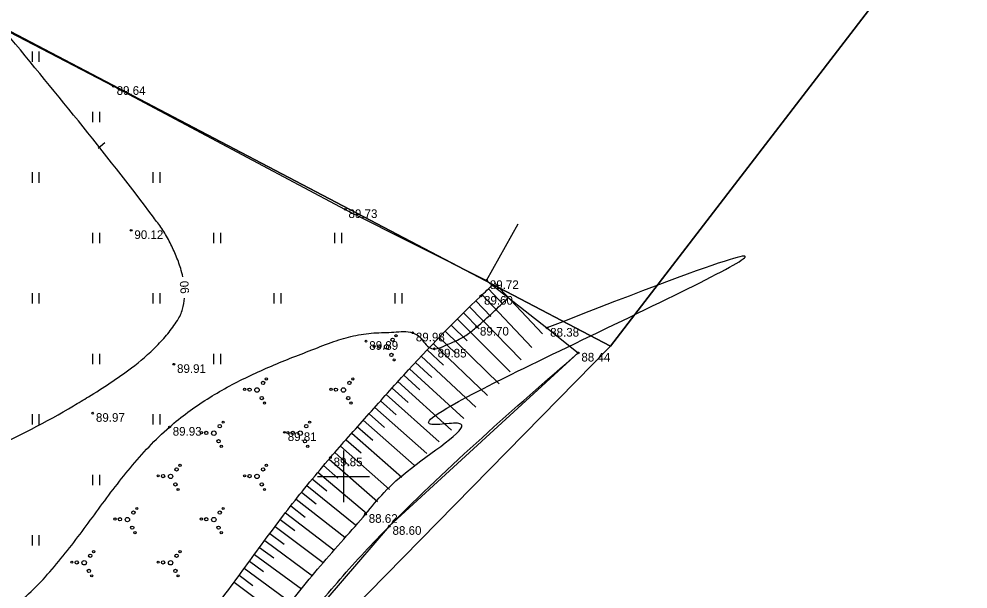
# Model space of a CAD drawing. Extents: x 635228 to 635525, y 248590 to 248800.
# Drawn here: x 635431.2 to 635486.1, y 248693.5 to 248726.5 of the extents above; entities that cross this region are included whole.
import ezdxf

# ---------------------------------------------------------------- set-up
doc = ezdxf.new("R2010")
doc.units = 0
for name, color, linetype in [('GEOD_ELEM_####_####_#', 7, 'Continuous'), ('HIDG_GRAV_####_####_#', 7, 'Continuous'), ('NORB_ZOGS_ZSTP_####_#', 7, 'Continuous'), ('RAMI_UZMR_####_####_#', 7, 'Continuous'), ('RELJ_AATZ_####_TKST_#', 7, 'Continuous'), ('RELJ_ELEM_####_####_#', 7, 'Continuous'), ('RELJ_HORZ_####_TKST_#', 7, 'Continuous'), ('RELJ_HORZ_RESN_####_#', 7, 'Continuous'), ('RELJ_NOGA_####_####_#', 7, 'Continuous'), ('ROBZ_IERR_####_####_#', 7, 'Continuous'), ('ROBZ_UZMR_####_####_#', 7, 'Continuous'), ('TERT_ELEM_####_####_#', 7, 'Continuous'), ('TERT_KONT_####_####_#', 7, 'Continuous')]:
    doc.layers.add(name, color=color, linetype=linetype)

msp = doc.modelspace()

# ---------------------------------------------------------------- linework, layer by layer
at = {"layer": 'GEOD_ELEM_####_####_#'}
for p, q in [((635450, 248701.5), (635450, 248700)), ((635448.5, 248700), (635450, 248700)), ((635450, 248700), (635450, 248698.5)), ((635450, 248700), (635451.5, 248700))]:
    msp.add_line(p, q, dxfattribs=at)
at = {"layer": 'HIDG_GRAV_####_####_#'}
for points in [[(635394.244, 248623.295), (635394.9074355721, 248630.6631552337), (635396.5650242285, 248636.944974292), (635397.8888882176, 248639.97580624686), (635399.2686043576, 248642.98780740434), (635400.0423829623, 248644.69884236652), (635400.835233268, 248646.3905777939), (635402.4795660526, 248649.72803076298), (635404.20443685, 248653.0239277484), (635406.0126797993, 248656.30203018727), (635407.0670223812, 248658.14081276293), (635408.1930324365, 248659.92698593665), (635409.4621962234, 248661.60192368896), (635410.172800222, 248662.37935865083), (635410.946, 248663.10700000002), (635413.0008032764, 248664.6744257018), (635415.1640977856, 248666.05372522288), (635417.3478434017, 248667.38916213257), (635419.464, 248668.825), (635422.2083511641, 248670.85354035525), (635424.965867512, 248672.86854694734), (635430.4558647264, 248676.93578902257), (635435.8049295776, 248681.1823865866), (635438.3862804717, 248683.4215875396), (635439.6466024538, 248684.57867623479), (635440.8840000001, 248685.76400000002), (635443.6087249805, 248688.6747140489), (635446.1599310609, 248691.73220612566), (635448.6719216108, 248694.81834513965), (635451.279, 248697.815), (635453.9336502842, 248700.48189136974), (635456.6811388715, 248703.07136968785), (635459.3523080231, 248705.7266631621), (635461.7780000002, 248708.59100000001), (635461.778, 248708.59100000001)], [(635396.7397638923, 248625.2320466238), (635397.9986579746, 248634.27312358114), (635398.9188026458, 248636.96227546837), (635399.5920874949, 248638.24717771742), (635399.9292604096, 248638.88899780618), (635400.2466831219, 248639.53584001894), (635401.591165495, 248642.41958219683), (635402.9524948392, 248645.2868638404), (635405.8217854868, 248650.96088254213), (635407.5583128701, 248653.91205967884), (635409.4799859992, 248656.7354955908), (635411.5283407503, 248659.48290512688), (635413.6449129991, 248662.20600313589), (635414.8182615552, 248663.6538935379), (635415.4704678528, 248664.3057478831), (635416.2076616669, 248664.85985159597), (635417.1601741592, 248665.41138033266), (635418.1313630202, 248665.91742947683), (635419.1067857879, 248666.41122678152), (635420.072, 248666.926), (635421.5645353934, 248667.7418115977), (635423.0692260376, 248668.5354410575), (635426.0762392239, 248670.12612318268), (635429.0153718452, 248671.8379856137), (635430.4352117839, 248672.78309045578), (635431.128452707, 248673.2855892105), (635431.8089561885, 248673.81096758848), (635433.1953696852, 248675.0040709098), (635434.526751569, 248676.2563297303), (635437.0226234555, 248678.92292892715), (635441.762, 248684.467), (635443.1273679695, 248686.0473501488), (635444.4678763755, 248687.6485508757), (635447.1219662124, 248690.87245996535), (635449.819572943, 248694.05663907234), (635451.2144774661, 248695.60817732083), (635452.6560000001, 248697.119), (635458.0231966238, 248702.2419696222), (635463.584, 248707.15000000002)]]:
    msp.add_spline(points, degree=3, dxfattribs=at)
at = {"layer": 'NORB_ZOGS_ZSTP_####_#'}
msp.add_lwpolyline([(635360.648, 248762.312), (635368.914, 248758.068), (635380.222, 248751.913), (635388.377, 248747.78900000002), (635390.826, 248746.16), (635396.2860000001, 248743.48500000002), (635409.766, 248736.46000000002), (635417.8699999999, 248732.30000000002), (635426.003, 248728.155), (635436.69, 248722.584), (635450.108, 248715.45700000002), (635458.287, 248711.34600000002), (635460.1128222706, 248714.62474159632)], dxfattribs=at)
at = {"layer": 'RAMI_UZMR_####_####_#'}
msp.add_lwpolyline([(635426.003, 248728.15499999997), (635436.69, 248722.584), (635450.108, 248715.45700000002), (635458.287, 248711.34600000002), (635461.7780000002, 248708.59100000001), (635463.584, 248707.15000000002), (635452.6560000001, 248697.119), (635441.762, 248684.467), (635435.9528772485, 248677.73413872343), (635432.018527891, 248673.97985762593), (635429.363741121, 248672.06248825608), (635427.0556775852, 248670.66460585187), (635420.072, 248666.926), (635415.05332695, 248664.00973325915), (635408.095218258, 248654.65947737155), (635398.6701763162, 248636.43948679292), (635398.046283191, 248634.41686083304), (635396.3166782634, 248622.87374513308), (635394.244, 248623.295), (635390.206, 248622.483), (635381.566, 248626.41900000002), (635379.918, 248627.738), (635364.657, 248634.36500000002)], dxfattribs=at)
at = {"layer": 'RELJ_ELEM_####_####_#'}
for centre in [(635436.69, 248722.584), (635450.108, 248715.45700000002), (635437.718, 248714.24300000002), (635458.287, 248711.34600000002), (635457.9500000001, 248710.44), (635457.714, 248708.652), (635454.0060000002, 248708.314), (635461.7780000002, 248708.59100000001), (635451.3080000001, 248707.82700000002), (635455.2640000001, 248707.383), (635463.584, 248707.15000000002), (635440.186, 248706.49000000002), (635435.4920000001, 248703.66100000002), (635439.936, 248702.85900000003), (635446.592, 248702.548), (635449.246, 248701.08800000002), (635451.279, 248697.815), (635452.6560000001, 248697.119)]:
    msp.add_circle(centre, 0.05, dxfattribs=at)
at = {"layer": 'RELJ_HORZ_RESN_####_#'}
msp.add_line((635435.8087515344, 248719.00655734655), (635436.1954663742, 248719.3234984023), dxfattribs=at)
for points in [[(635440.7152590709, 248711.54364329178), (635440.583994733, 248712.0305760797), (635440.2877567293, 248712.84067206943), (635440.1114035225, 248713.2345290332), (635439.9182199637, 248713.62218880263), (635439.7116635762, 248713.99309363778), (635439.4829756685, 248714.34956084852), (635439.0131516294, 248714.99704480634), (635430.1817186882, 248726.04739434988)], [(635396.8403365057, 248673.83023932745), (635398.5699520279, 248674.74721849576), (635400.1196081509, 248675.6687893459), (635401.3847631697, 248676.59316814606), (635401.8779834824, 248677.05585311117), (635402.2608753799, 248677.51857116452), (635402.5005008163, 248677.92779942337), (635402.9962003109, 248679.47940420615), (635403.1093939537, 248680.10527297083), (635403.2077718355, 248680.73304831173), (635403.3050539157, 248681.36081107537), (635403.4149601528, 248681.98664210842), (635403.9947087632, 248684.49620174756), (635404.4941894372, 248685.58182624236), (635404.822447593, 248686.0525951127), (635405.213, 248686.464), (635405.5227683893, 248686.49325254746), (635405.8948771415, 248686.27621660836), (635406.269797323, 248686.04907236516), (635406.588, 248686.048), (635407.1331532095, 248686.47133617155), (635407.6549224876, 248686.94769115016), (635408.6437981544, 248688.02779111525), (635410.511320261, 248690.47588617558), (635412.43838879, 248692.8856225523), (635414.0718482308, 248694.36296271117), (635414.672826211, 248694.7503376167), (635415.8418707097, 248695.38166460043), (635417.0157559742, 248695.99905223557), (635418.2014500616, 248696.5900310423), (635419.4059210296, 248697.14213154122), (635424.3998390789, 248699.29274669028), (635429.4588912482, 248701.50672660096), (635434.3873884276, 248704.0886148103), (635435.2434356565, 248704.60530447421), (635437.7315604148, 248706.27775516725), (635439.1970704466, 248707.5552960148), (635439.8338858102, 248708.26101524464), (635440.1227716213, 248708.63326282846), (635440.3898668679, 248709.01944554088), (635440.6922176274, 248709.6864690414), (635440.8034457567, 248710.32396866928)]]:
    msp.add_spline(points, degree=3, dxfattribs=at)
at = {"layer": 'RELJ_NOGA_####_####_#'}
for p, q in [((635458.7507877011, 248711.19532031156), (635461.5238321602, 248708.25534919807)), ((635458.0233306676, 248710.50916707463), (635460.8935670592, 248707.46615344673)), ((635458.3870591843, 248710.85224369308), (635459.2344702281, 248709.95382175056)), ((635457.300320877, 248709.81834287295), (635460.2761169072, 248706.74168752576)), ((635457.6605747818, 248710.16506404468), (635458.5384371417, 248709.24577131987)), ((635456.9427630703, 248709.4688411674), (635457.8515891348, 248708.54806386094)), ((635456.235110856, 248708.7622913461), (635457.1651303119, 248707.84622144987)), ((635456.587777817, 248709.11672723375), (635459.6533072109, 248706.04980383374)), ((635455.8847228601, 248708.4056016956), (635459.0067916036, 248705.36405206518)), ((635455.1904612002, 248707.6858868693), (635458.3372570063, 248704.6810007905)), ((635455.5365799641, 248708.046720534), (635456.4775242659, 248707.13883727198)), ((635454.8462935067, 248707.323191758), (635455.7922926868, 248706.42977421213)), ((635454.163237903, 248706.5928310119), (635455.1072428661, 248705.7167618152)), ((635454.5039056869, 248706.95881586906), (635457.6602966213, 248704.01217346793)), ((635453.8240771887, 248706.22544912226), (635456.9668449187, 248703.34344324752)), ((635453.1500941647, 248705.4867055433), (635456.2571430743, 248702.6705633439)), ((635453.4864578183, 248705.8566501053), (635454.4243257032, 248705.00166388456)), ((635452.8148920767, 248705.11570812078), (635453.7405111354, 248704.28141863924)), ((635452.1475016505, 248704.3710021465), (635453.058311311, 248703.55834299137)), ((635452.4807379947, 248704.74376640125), (635455.5423008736, 248701.99880622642)), ((635451.8150410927, 248703.99754573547), (635454.8240796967, 248701.32432924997)), ((635451.151874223, 248703.24907477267), (635454.1034339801, 248700.6434777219)), ((635451.4832108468, 248703.62352902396), (635452.3774163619, 248702.83198464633)), ((635450.8209720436, 248702.8742364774), (635451.6968263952, 248702.10104409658)), ((635450.1597600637, 248702.12403739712), (635451.0186125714, 248701.36717193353)), ((635450.4903386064, 248702.49916114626), (635453.3816116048, 248699.95122112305)), ((635449.8291815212, 248701.74891364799), (635452.6661222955, 248699.2488540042)), ((635449.4983825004, 248701.3739843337), (635450.3421288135, 248700.62937430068)), ((635448.8397843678, 248700.62150309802), (635449.6838531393, 248699.89911624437)), ((635449.1677142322, 248700.99893990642), (635451.9659276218, 248698.53924921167)), ((635448.516127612, 248700.24039430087), (635451.3338193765, 248697.87381566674)), ((635447.8803787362, 248699.46851923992), (635450.7080955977, 248697.18907648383)), ((635448.1964122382, 248699.85597317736), (635449.0439914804, 248699.1597187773)), ((635447.5676195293, 248699.07841672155), (635448.4144601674, 248698.40464081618)), ((635446.9512072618, 248698.2910043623), (635447.7955734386, 248697.638391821)), ((635447.2580275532, 248698.68579560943), (635450.0798587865, 248696.47854608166)), ((635446.6468800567, 248697.89428786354), (635449.4540488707, 248695.7508122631)), ((635446.3447459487, 248697.49589845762), (635447.1844750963, 248696.86229181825)), ((635445.7457224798, 248696.69517077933), (635446.5780655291, 248696.07709253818)), ((635446.0444019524, 248697.09615736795), (635448.8344916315, 248695.01405130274)), ((635445.4481811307, 248696.29333885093), (635448.2067325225, 248694.25382652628)), ((635445.1515740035, 248695.8908166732), (635445.9750107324, 248695.28585710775)), ((635444.559867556, 248695.08466325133), (635445.3719592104, 248694.48898971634)), ((635444.8555944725, 248695.48783268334), (635447.5820261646, 248693.487980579)), ((635444.2640867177, 248694.6815334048), (635446.9501521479, 248692.7079483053)), ((635443.6711792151, 248693.87626334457), (635446.3164226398, 248691.9252376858)), ((635443.9679659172, 248694.2786532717), (635444.7669883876, 248693.68932628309))]:
    msp.add_line(p, q, dxfattribs=at)
msp.add_spline([(635390.206, 248622.483), (635392.6761559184, 248639.41621940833), (635395.6724652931, 248647.2597307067), (635397.9131924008, 248650.95381667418), (635399.048256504, 248652.79837067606), (635400.128, 248654.662), (635400.9493075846, 248656.2558432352), (635403.3016292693, 248661.16811378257), (635405.1862207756, 248664.14373210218), (635407.706, 248666.499), (635412.1610828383, 248669.3503906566), (635416.627, 248672.168), (635424.6828055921, 248677.31078055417), (635432.728, 248682.47600000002), (635436.7060689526, 248685.70428438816), (635438.5008534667, 248687.5575466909), (635440.2150000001, 248689.48700000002), (635442.5291182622, 248692.3528262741), (635444.7219287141, 248695.30565037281), (635446.9190248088, 248698.24939928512), (635449.246, 248701.08800000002), (635451.3600052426, 248703.48451832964), (635453.4937434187, 248705.86484004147), (635457.9500000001, 248710.44), (635458.6576193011, 248711.10744185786)], degree=3, dxfattribs=at)
at = {"layer": 'ROBZ_IERR_####_####_#'}
for points in [[(635390.8703529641, 248797.67647954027), (635383.3870000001, 248769.68700000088), (635386.4840000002, 248768.44700000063), (635478.3770000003, 248731.65799999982), (635482.5609999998, 248729.82799999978), (635465.4589999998, 248707.53900000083), (635458.6069999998, 248711.13399999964), (635360.483, 248762.61500000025), (635360.8880000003, 248769.91799999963), (635363.3208497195, 248797.67647954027)], [(635522.337313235, 248635.85405923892), (635430.9589999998, 248667.77300000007), (635424.5429999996, 248670.01400000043), (635439.4570000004, 248681.03800000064), (635465.4589999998, 248707.53900000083), (635482.5609999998, 248729.82799999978), (635498.1289999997, 248747.85500000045)]]:
    msp.add_lwpolyline(points, dxfattribs=at)
at = {"layer": 'ROBZ_UZMR_####_####_#'}
msp.add_lwpolyline([(635325.5420000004, 248659.74000000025), (635329.6529999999, 248676.3660000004), (635327.79, 248676.82799999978), (635337.4600999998, 248688.65990000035), (635343.3430000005, 248703.1199999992), (635360.483, 248762.61500000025), (635458.6069999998, 248711.13399999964), (635465.4589999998, 248707.53900000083), (635439.4570000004, 248681.03800000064), (635424.5429999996, 248670.01400000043), (635420.9790000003, 248667.37900000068), (635407.0700000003, 248653.17999999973), (635400.0669999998, 248641.1490000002), (635395.1619999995, 248617.53900000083), (635389.0310000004, 248621.06200000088), (635375.858, 248629.11500000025)], close=True, dxfattribs=at)
at = {"layer": 'TERT_ELEM_####_####_#'}
for p, q in [((635432, 248724), (635432, 248724.6)), ((635432.4, 248724), (635432.4, 248724.6)), ((635435.5, 248720.5), (635435.5, 248721.1)), ((635435.9, 248720.5), (635435.9, 248721.1)), ((635432, 248717), (635432, 248717.6)), ((635432.4, 248717), (635432.4, 248717.6)), ((635439, 248717), (635439, 248717.6)), ((635439.4, 248717), (635439.4, 248717.6)), ((635435.5, 248713.5), (635435.5, 248714.1)), ((635435.9, 248713.5), (635435.9, 248714.1)), ((635442.5, 248713.5), (635442.5, 248714.1)), ((635442.9, 248713.5), (635442.9, 248714.1)), ((635449.5, 248713.5), (635449.5, 248714.1)), ((635449.9, 248713.5), (635449.9, 248714.1)), ((635432, 248710), (635432, 248710.6)), ((635432.4, 248710), (635432.4, 248710.6)), ((635439, 248710), (635439, 248710.6)), ((635439.4, 248710), (635439.4, 248710.6)), ((635446, 248710), (635446, 248710.6)), ((635446.4, 248710), (635446.4, 248710.6)), ((635453, 248710), (635453, 248710.6)), ((635453.4, 248710), (635453.4, 248710.6)), ((635435.5, 248706.5), (635435.5, 248707.1)), ((635435.9, 248706.5), (635435.9, 248707.1)), ((635442.5, 248706.5), (635442.5, 248707.1)), ((635442.9, 248706.5), (635442.9, 248707.1)), ((635432, 248703), (635432, 248703.6)), ((635432.4, 248703), (635432.4, 248703.6)), ((635439, 248703), (635439, 248703.6)), ((635439.4, 248703), (635439.4, 248703.6)), ((635435.5, 248699.5), (635435.5, 248700.1)), ((635435.9, 248699.5), (635435.9, 248700.1)), ((635432, 248696), (635432, 248696.6)), ((635432.4, 248696), (635432.4, 248696.6))]:
    msp.add_line(p, q, dxfattribs=at)
for centre, radius in [((635453.044, 248708.13935999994), 0.06400000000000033), ((635452.06608, 248707.52079999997), 0.09600000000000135), ((635452.5, 248707.5), 0.12800000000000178), ((635452.8475200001, 248707.90767999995), 0.09600000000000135), ((635451.7816, 248707.53423999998), 0.06400000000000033), ((635452.77648, 248707.03311999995), 0.09600000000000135), ((635452.93392, 248706.74383999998), 0.06400000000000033), ((635445.3475200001, 248705.40767999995), 0.09600000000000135), ((635445.544, 248705.63935999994), 0.06400000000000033), ((635450.3475200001, 248705.40767999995), 0.09600000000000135), ((635450.544, 248705.63935999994), 0.06400000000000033), ((635444.2816, 248705.03423999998), 0.06400000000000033), ((635444.56608, 248705.02079999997), 0.09600000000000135), ((635445, 248705), 0.12800000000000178), ((635449.2816, 248705.03423999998), 0.06400000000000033), ((635449.56608, 248705.02079999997), 0.09600000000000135), ((635450, 248705), 0.12800000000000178), ((635445.27648, 248704.53311999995), 0.09600000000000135), ((635445.43392, 248704.24383999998), 0.06400000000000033), ((635450.27648, 248704.53311999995), 0.09600000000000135), ((635450.43392, 248704.24383999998), 0.06400000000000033), ((635442.8475200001, 248702.90767999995), 0.09600000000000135), ((635443.044, 248703.13935999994), 0.06400000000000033), ((635447.8475200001, 248702.90767999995), 0.09600000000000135), ((635448.044, 248703.13935999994), 0.06400000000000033), ((635441.7816, 248702.53423999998), 0.06400000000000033), ((635442.06608, 248702.52079999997), 0.09600000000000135), ((635442.5, 248702.5), 0.12800000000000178), ((635442.77648, 248702.03311999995), 0.09600000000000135), ((635446.7816, 248702.53423999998), 0.06400000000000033), ((635447.06608, 248702.52079999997), 0.09600000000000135), ((635447.5, 248702.5), 0.12800000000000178), ((635447.77648, 248702.03311999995), 0.09600000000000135), ((635442.93392, 248701.74383999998), 0.06400000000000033), ((635447.93392, 248701.74383999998), 0.06400000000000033), ((635440.3475200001, 248700.40767999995), 0.09600000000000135), ((635440.544, 248700.63935999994), 0.06400000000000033), ((635445.3475200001, 248700.40767999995), 0.09600000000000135), ((635445.544, 248700.63935999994), 0.06400000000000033), ((635439.2816, 248700.03423999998), 0.06400000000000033), ((635439.56608, 248700.02079999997), 0.09600000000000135), ((635440, 248700), 0.12800000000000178), ((635444.2816, 248700.03423999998), 0.06400000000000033), ((635444.56608, 248700.02079999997), 0.09600000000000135), ((635445, 248700), 0.12800000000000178), ((635440.27648, 248699.53311999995), 0.09600000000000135), ((635445.27648, 248699.53311999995), 0.09600000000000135), ((635440.43392, 248699.24383999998), 0.06400000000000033), ((635445.43392, 248699.24383999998), 0.06400000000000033), ((635437.8475200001, 248697.90767999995), 0.09600000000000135), ((635438.044, 248698.13935999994), 0.06400000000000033), ((635442.8475200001, 248697.90767999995), 0.09600000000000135), ((635443.044, 248698.13935999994), 0.06400000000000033), ((635436.7816, 248697.53423999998), 0.06400000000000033), ((635437.06608, 248697.52079999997), 0.09600000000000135), ((635437.5, 248697.5), 0.12800000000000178), ((635441.7816, 248697.53423999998), 0.06400000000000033), ((635442.06608, 248697.52079999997), 0.09600000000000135), ((635442.5, 248697.5), 0.12800000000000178), ((635437.77648, 248697.03311999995), 0.09600000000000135), ((635437.93392, 248696.74383999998), 0.06400000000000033), ((635442.77648, 248697.03311999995), 0.09600000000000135), ((635442.93392, 248696.74383999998), 0.06400000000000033), ((635435.544, 248695.63935999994), 0.06400000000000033), ((635440.544, 248695.63935999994), 0.06400000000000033), ((635434.2816, 248695.03423999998), 0.06400000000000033), ((635434.56608, 248695.02079999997), 0.09600000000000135), ((635435, 248695), 0.12800000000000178), ((635435.3475200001, 248695.40767999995), 0.09600000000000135), ((635439.2816, 248695.03423999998), 0.06400000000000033), ((635439.56608, 248695.02079999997), 0.09600000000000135), ((635440, 248695), 0.12800000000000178), ((635440.3475200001, 248695.40767999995), 0.09600000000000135), ((635435.27648, 248694.53311999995), 0.09600000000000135), ((635440.27648, 248694.53311999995), 0.09600000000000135), ((635435.43392, 248694.24383999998), 0.06400000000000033), ((635440.43392, 248694.24383999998), 0.06400000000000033)]:
    msp.add_circle(centre, radius, dxfattribs=at)
at = {"layer": 'TERT_KONT_####_####_#'}
msp.add_spline([(635381.566, 248626.41900000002), (635384.141, 248634.765), (635385.389202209, 248637.7914590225), (635387.0292419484, 248640.6516206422), (635388.8146607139, 248643.4497219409), (635389.6848689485, 248644.8580740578), (635390.4990000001, 248646.29), (635392.0226550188, 248649.21918285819), (635393.5071185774, 248652.1702394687), (635395.0017728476, 248655.12192634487), (635396.556, 248658.053), (635399.9011134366, 248663.08488427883), (635403.9259848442, 248667.61643358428), (635408.395257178, 248671.78623589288), (635410.7229946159, 248673.7787906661), (635413.0735733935, 248675.7328791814), (635414.4692599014, 248676.62068389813), (635415.9938205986, 248677.30794837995), (635417.5018643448, 248678.0054584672), (635418.848, 248678.924), (635420.219040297, 248680.28079949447), (635421.4913245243, 248681.74225536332), (635423.8682567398, 248684.84208090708), (635426.2360605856, 248687.94936599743), (635428.1606833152, 248690.11983046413), (635428.8520000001, 248690.79), (635429.5317929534, 248691.3720486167), (635430.2428233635, 248691.92597447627), (635430.954192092, 248692.47941309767), (635431.635, 248693.06), (635432.7520114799, 248694.18745503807), (635433.7815998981, 248695.39485218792), (635435.7079899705, 248697.94525714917), (635437.6731350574, 248700.50278353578), (635438.7511672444, 248701.71908246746), (635439.936, 248702.85900000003), (635442.1191491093, 248704.47891720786), (635444.4652000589, 248705.76616705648), (635446.9243060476, 248706.83607415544), (635448.1806775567, 248707.32556311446), (635449.4466202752, 248707.80396311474), (635450.5789798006, 248708.1275799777), (635451.7602437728, 248708.30057270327), (635452.9245409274, 248708.35276985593), (635454.0060000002, 248708.314), (635454.3355621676, 248708.1390314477), (635454.6423695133, 248707.79518323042), (635454.9454921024, 248707.47799339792), (635455.2640000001, 248707.383), (635455.8819855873, 248707.57371461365), (635456.5298319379, 248707.8540188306), (635457.157262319, 248708.21606363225), (635457.714, 248708.652), (635459.5420464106, 248710.35555231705)], degree=3, dxfattribs=at)

# ---------------------------------------------------------------- texts
at = {"layer": 'RELJ_AATZ_####_TKST_#'}
for s, p in [(' 89.64', (635436.69, 248722.084)), (' 89.73', (635450.108, 248714.95700000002)), (' 90.12', (635437.718, 248713.74300000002)), (' 89.72', (635458.287, 248710.84600000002)), (' 89.60', (635457.9500000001, 248709.94)), (' 89.98', (635454.0060000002, 248707.814)), (' 89.70', (635457.714, 248708.152)), (' 88.38', (635461.7780000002, 248708.09100000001)), (' 89.89', (635451.3080000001, 248707.32700000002)), (' 89.85', (635455.2640000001, 248706.883)), (' 88.44', (635463.584, 248706.65000000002)), (' 89.91', (635440.186, 248705.99000000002)), (' 89.97', (635435.4920000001, 248703.16100000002)), (' 89.93', (635439.936, 248702.35900000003)), (' 89.81', (635446.592, 248702.048)), (' 89.85', (635449.246, 248700.58800000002)), (' 88.62', (635451.279, 248697.315)), (' 88.60', (635452.6560000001, 248696.619))]:
    msp.add_text(s, height=0.5, dxfattribs=at).set_placement(p)
at = {"layer": 'RELJ_HORZ_####_TKST_#'}
msp.add_text('90', height=0.49999999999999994, rotation=94.31579699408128, dxfattribs=at).set_placement((635441.0797054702, 248710.59552825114))

doc.saveas('drawing.dxf')
